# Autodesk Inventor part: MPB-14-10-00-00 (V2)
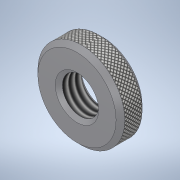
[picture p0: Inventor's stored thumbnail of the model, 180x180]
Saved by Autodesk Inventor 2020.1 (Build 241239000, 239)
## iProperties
Created: 2020-04
Part Number: MPB-14-10-00-00 (V2)
Material: St-37
Document SubType Name: Modeling
Designer: Safarabadi
Density: 7.85 g/cm^3
Appearance: St-37
Author: Safarabadi
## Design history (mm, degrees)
derived "MPB-14-10-00-00.ipt"
feature "Solid1::MPB-14-10-00-00.ipt" dims "d0" = 10
tag "TaggingFeature1"
body "Solid1"
